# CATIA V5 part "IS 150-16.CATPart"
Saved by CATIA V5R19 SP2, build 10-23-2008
Part number: IS 150-16
Bounding box of the stored display mesh (mm): x -15.868 to 15.868, y -15.868 to 15.868, z 0 to 82
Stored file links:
  C:\Users\Bora\Desktop\3D Katı model\IS serisi\IS 150\IS 150-16.CATPart
  C:\Program Files\Dassault Systemes\B19\intel_a\reffiles\standard\MetricThinPitch.txt
  C:\Program Files\Dassault Systemes\B19\intel_a\reffiles\standard\MetricThickPitch.txt
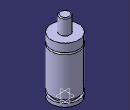
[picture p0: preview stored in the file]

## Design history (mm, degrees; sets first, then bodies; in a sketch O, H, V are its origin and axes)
Body1 (main body)
  Sketch1 on yz-plane, origin (0, 0, 0), H (0, 1, 0), V (0, 0, 1)
    point P3 (6, 81)
    point P5 (6, 81)
    point P7 (16, 54.5)
    point P8 (16, 52.5)
    point P12 (16, 52.5)
    point P13 (16, 54.5)
    line L1 (16, 0) -> (16, 4)
    line L2 (6, 81) -> (6, 64)
    arc A1 centre (5, 81) radius 1 from (6, 81) to (5, 82) ccw
    arc A2 centre (16, 53.5) radius 1 from (16, 54.5) to (16, 52.5) ccw
    line L3 (13.5, 7.5) -> (13.5, 4)
    line L4 (16, 7.5) -> (16, 52.5)
    line L5 (16, 54.5) -> (16, 64)
    line L6 (0, 0) -> (16, 0)
    line L7 (13.5, 4) -> (16, 4)
    line L8 (13.5, 7.5) -> (16, 7.5)
    line L9 (6, 64) -> (16, 64)
    line L10 (5, 82) -> (0, 82)
    point P15 (0, 82)
    horizontal: L6 H, L7 H, L8 H, L9 H
    tangency: L10 A1
    coincidence: P15 V, P3 P5, P7 P13, P8 P12
  Shaft1: profile Sketch1, axis Sketch1.V, angle 360
  Sketch2 on face of Shaft1 from Sketch1.L6, origin (0, 0, 0), H (1, 0, 0), V (0, -1, 0)
    point P1 (0, 0)
  Hole1: placed by Sketch2, at (0, 0, 0) direction (0, 0, 1), diameter 6.647, depth 7, threaded "M8", thread diameter 8, thread depth 7, pitch 1.25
